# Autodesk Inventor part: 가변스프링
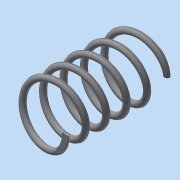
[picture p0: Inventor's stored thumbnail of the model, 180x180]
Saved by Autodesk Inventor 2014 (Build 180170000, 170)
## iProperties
Created: 2024-02
Part Number: 가변스프링
Material: 스테인레스 스틸
Document SubType Name: Modeling
Designer: dg
Density: 8.08 g/cm^3
Appearance: 반연마
Author: dg
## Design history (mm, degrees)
sketch "스케치1"
  geometry: L1 (0, 0)-(-9, 0); L2 (-9, 0)-(-9, 28.5); L3 (-9, 28.5)-(0, 28.5); C1 r 1 at (0, 0); 1 further point
  constraints: 6 end point, 2 parallel, 1 centre point, 1 coincident, 1 horizontal, 1 perpendicular
  dimensions: "d0" = 2 diameter of C1; "d1" = 9 distance of L1.start L1.end; "d2" = 28.5 distance of L1.end L2.end (derived)
feature "코일1" sketch "스케치1" pitch "d3" = 10; turns "d5" = 5; dims "d4" = 28.5 (= d2), "d6" = 0, angle "d7" = 90 deg, angle "d8" = 90 deg, "d9" = 0, "d10" = 0
feature "분할1"
node "작업 평면1"
feature "분할2"
node "솔리드1"
other parameters: "d11" = 0
